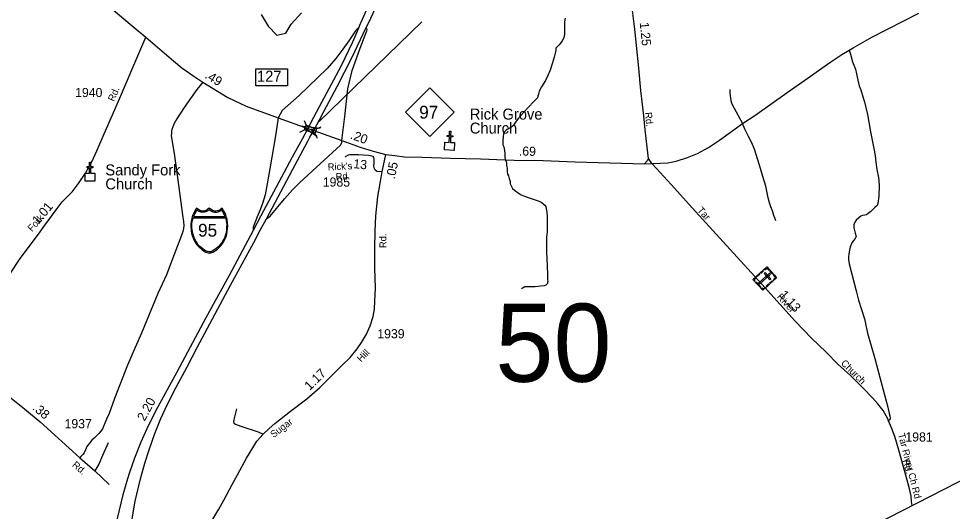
# Model space of a CAD drawing. Extents: x 2220236 to 2384410, y 720751 to 894131.
# Drawn here: x 2299448 to 2312183, y 756055 to 762781 of the extents above; entities that cross this region are included whole.
import ezdxf

# ---------------------------------------------------------------- set-up
doc = ezdxf.new("R2010")
doc.units = 0
for name, color, linetype in [('Exist Boundary Political CountyLine', 7, 'Continuous'), ('Exist Cultural Cemetery CELL', 7, 'Continuous'), ('Exist Cultural Church CELL', 7, 'Continuous'), ('Exist Cultural Church Label', 7, 'Continuous'), ('Exist Hydrographic Pond Under 1500 Sq Ft', 7, 'Continuous'), ('Exist Road Non-System Type 51', 7, 'Continuous'), ('Exist Road Non-System Type 51 Label', 7, 'Continuous'), ('Exist Road Primary Interstate Divided Center Attributed', 7, 'Continuous'), ('Exist Road Primary Interstate Interchange CELL', 7, 'Continuous'), ('Exist Road Primary Interstate Mileage Hundredths English Label', 7, 'Continuous'), ('Exist Road Primary Interstate Ramp 1 Lane Attributed', 7, 'Continuous'), ('Exist Road Primary Interstate Shield CELL', 7, 'Continuous'), ('Exist Road Primary Interstate Shield Number Label', 7, 'Continuous'), ('Exist Road Primary NC Attributed', 7, 'Continuous'), ('Exist Road Primary NC Service Mileage Hundredths English Label', 7, 'Continuous'), ('Exist Road Primary NC Shield CELL', 7, 'Continuous'), ('Exist Road Primary NC Shield Number Label', 7, 'Continuous'), ('Exist Road Primary NC Structure Standard Bridge CELL', 7, 'Continuous'), ('Exist Road Secondary Mileage Hundredths English Label', 7, 'Continuous'), ('Exist Road Secondary Structure Standard Bridge Attributed CELL', 7, 'Continuous'), ('Exist Road Secondary Structure Standard Bridge Number Label', 7, 'Continuous'), ('Exist Road Secondary Type 51 Attributed', 7, 'Continuous'), ('Exist Road Secondary Type 51 Label', 7, 'Continuous'), ('Exist Road Secondary Type 51 Number Label', 7, 'Continuous')]:
    doc.layers.add(name, color=color, linetype=linetype)

msp = doc.modelspace()

# ---------------------------------------------------------------- linework, layer by layer
at = {"layer": 'Exist Boundary Political CountyLine'}
msp.add_lwpolyline([(2324918, 762929), (2323369, 762135), (2322391, 761632), (2321693, 761275), (2320800, 760815), (2319981, 760403), (2317987, 759382), (2316918, 758831), (2315940, 758332), (2312438, 756546), (2310566, 755586), (2308713, 754646), (2307603, 754075), (2306331, 753423), (2305629, 753064), (2303724, 752098), (2302269, 751355), (2301514, 750963), (2300820, 750611), (2300140, 750264), (2297549, 748943)], dxfattribs=at)
at = {"layer": 'Exist Cultural Cemetery CELL'}
for points in [[(2309652, 759392), (2309786, 759245), (2309598, 759073), (2309464, 759220)], [(2309620, 759363), (2309627, 759354), (2309651, 759376), (2309678, 759346), (2309687, 759354), (2309652, 759392)], [(2309515, 759267), (2309547, 759297), (2309555, 759288), (2309523, 759259)], [(2309704, 759292), (2309691, 759306), (2309541, 759169), (2309554, 759155)], [(2309565, 759313), (2309597, 759342), (2309604, 759334), (2309573, 759304)], [(2309629, 759316), (2309615, 759303), (2309695, 759217), (2309708, 759229)], [(2309702, 759337), (2309737, 759299), (2309728, 759292), (2309693, 759330)], [(2309754, 759216), (2309746, 759224), (2309770, 759246), (2309743, 759276), (2309751, 759283), (2309786, 759245)], [(2309486, 759196), (2309495, 759204), (2309480, 759220), (2309510, 759247), (2309502, 759255), (2309464, 759220)], [(2309511, 759185), (2309568, 759123), (2309560, 759115), (2309503, 759178)], [(2309644, 759130), (2309676, 759160), (2309683, 759151), (2309651, 759122)], [(2309692, 759175), (2309724, 759204), (2309732, 759196), (2309700, 759167)], [(2309576, 759098), (2309584, 759105), (2309599, 759089), (2309629, 759117), (2309636, 759108), (2309598, 759073)]]:
    msp.add_lwpolyline(points, close=True, dxfattribs=at)
at = {"layer": 'Exist Cultural Church CELL'}
for points in [[(2305263, 761094), (2305320, 761092), (2305323, 761168), (2305291, 761170), (2305291, 761186), (2305323, 761184), (2305326, 761244), (2305342, 761244), (2305339, 761184), (2305371, 761182), (2305371, 761166), (2305339, 761168), (2305336, 761092), (2305393, 761089), (2305389, 760983), (2305258, 760988)], [(2300356, 760670), (2300413, 760670), (2300413, 760746), (2300381, 760746), (2300381, 760762), (2300413, 760762), (2300413, 760822), (2300429, 760822), (2300429, 760762), (2300461, 760762), (2300461, 760746), (2300429, 760746), (2300429, 760670), (2300487, 760670), (2300487, 760563), (2300356, 760563)]]:
    msp.add_lwpolyline(points, close=True, dxfattribs=at)
at = {"layer": 'Exist Hydrographic Pond Under 1500 Sq Ft'}
for points in [[(2302756, 762838), (2302849, 762677), (2302967, 762554)], [(2302967, 762554), (2303092, 762582), (2303166, 762707), (2303306, 762860)]]:
    msp.add_lwpolyline(points, dxfattribs=at)
at = {"layer": 'Exist Road Non-System Type 51'}
msp.add_line((2300683, 756421), (2300487, 756607), dxfattribs=at)
for points in [[(2306903, 762788), (2306892, 762741), (2306891, 762695), (2306891, 762641), (2306892, 762598), (2306891, 762569), (2306882, 762519), (2306863, 762478), (2306840, 762445), (2306819, 762423), (2306794, 762396), (2306773, 762377), (2306773, 762353), (2306767, 762310), (2306753, 762257), (2306724, 762164), (2306698, 762076), (2306666, 762005), (2306632, 761935), (2306581, 761852), (2306547, 761792), (2306544, 761775), (2306537, 761747), (2306531, 761722), (2306523, 761701), (2306508, 761684), (2306472, 761645), (2306336, 761500), (2306264, 761424), (2306234, 761382), (2306214, 761353), (2306198, 761329), (2306189, 761316), (2306172, 761300), (2306142, 761288), (2306120, 761273), (2306096, 761258), (2306083, 761245), (2306072, 761230), (2306062, 761205), (2306058, 761170), (2306051, 761111), (2306053, 761060), (2306067, 761029), (2306075, 760982), (2306078, 760941), (2306080, 760903), (2306082, 760855)], [(2310776, 762352), (2310796, 762295), (2310823, 762190), (2310864, 762092), (2310876, 762030), (2310896, 761940), (2310913, 761866), (2310933, 761809), (2310968, 761702), (2310986, 761647), (2311000, 761586), (2311026, 761472), (2311044, 761367), (2311068, 761237), (2311104, 761055), (2311119, 760985), (2311130, 760907), (2311138, 760824), (2311154, 760721), (2311175, 760611), (2311183, 760508), (2311179, 760359), (2311169, 760256), (2311157, 760232), (2311127, 760202), (2311073, 760147), (2311037, 760119), (2311011, 760105), (2310989, 760098), (2310957, 760092), (2310934, 760083), (2310907, 760061), (2310873, 760030), (2310847, 759995), (2310841, 759966), (2310838, 759926), (2310847, 759891), (2310857, 759853), (2310871, 759808), (2310868, 759796), (2310859, 759782), (2310834, 759754), (2310813, 759719), (2310790, 759665), (2310776, 759600), (2310772, 759565), (2310768, 759530), (2310768, 759495), (2310776, 759434), (2310809, 759310), (2310873, 759065), (2310904, 758937), (2310983, 758683), (2311026, 758487), (2311127, 758142), (2311207, 757834), (2311302, 757479), (2311321, 757393), (2311331, 757357), (2311334, 757324), (2311333, 757314), (2311327, 757303), (2311314, 757290)], [(2301961, 761913), (2301880, 761815), (2301707, 761570), (2301607, 761415), (2301568, 761348), (2301549, 761304), (2301538, 761269), (2301531, 761246), (2301531, 761213), (2301529, 761181), (2301568, 760939), (2301623, 760545), (2301688, 760066), (2301697, 760011), (2301700, 759958), (2301695, 759916), (2301686, 759877), (2301658, 759796), (2301570, 759560), (2301464, 759282), (2301346, 759028), (2301198, 758667), (2301124, 758487), (2301036, 758293), (2300934, 758050), (2300756, 757596), (2300684, 757390), (2300647, 757314), (2300615, 757235), (2300590, 757182), (2300569, 757149), (2300542, 757118), (2300510, 757086), (2300481, 757059), (2300444, 757027), (2300416, 756987), (2300379, 756939), (2300358, 756897), (2300340, 756855), (2300324, 756832), (2300298, 756805), (2300283, 756786)], [(2309149, 761812), (2309150, 761764), (2309161, 761664), (2309169, 761634), (2309184, 761598), (2309206, 761560), (2309323, 761348)], [(2309776, 760023), (2309763, 760064), (2309749, 760094), (2309737, 760126), (2309728, 760156), (2309709, 760211), (2309687, 760267), (2309669, 760336), (2309659, 760405), (2309638, 760494), (2309596, 760627), (2309551, 760783), (2309527, 760869), (2309489, 760985), (2309447, 761086), (2309401, 761172), (2309354, 761271), (2309323, 761348)], [(2306082, 760855), (2306096, 760830), (2306103, 760811), (2306104, 760777), (2306109, 760740), (2306110, 760696), (2306117, 760660), (2306129, 760635), (2306139, 760600), (2306142, 760584), (2306150, 760559), (2306154, 760525), (2306166, 760497), (2306185, 760464), (2306213, 760438), (2306260, 760405), (2306302, 760378), (2306346, 760357), (2306409, 760333), (2306481, 760313), (2306536, 760295), (2306573, 760278), (2306595, 760262), (2306608, 760250), (2306623, 760237), (2306637, 760215), (2306644, 760184), (2306652, 760140), (2306656, 760079), (2306658, 759987), (2306657, 759873), (2306649, 759799), (2306648, 759676), (2306649, 759594), (2306656, 759414), (2306660, 759277), (2306662, 759221), (2306664, 759192), (2306662, 759179), (2306660, 759166), (2306649, 759151), (2306637, 759141), (2306616, 759133), (2306565, 759128), (2306494, 759121), (2306384, 759121), (2306350, 759118), (2306329, 759108), (2306311, 759095), (2306306, 759089)], [(2308038, 760873), (2308021, 760842), (2307984, 760801)], [(2302417, 757456), (2302394, 757345), (2302377, 757280), (2302383, 757257), (2302405, 757246), (2302479, 757216), (2302713, 757139), (2302781, 757109)], [(2300667, 756991), (2300593, 756816), (2300540, 756699), (2300487, 756607)]]:
    msp.add_lwpolyline(points, dxfattribs=at)
at = {"layer": 'Exist Road Primary Interstate Divided Center Attributed'}
for points in [[(2305039, 765388), (2304961, 765138), (2304756, 764498), (2304486, 763661), (2304332, 763236), (2304205, 762933), (2304113, 762728), (2304106, 762711), (2304081, 762649)], [(2304190, 762659), (2304219, 762721), (2304283, 762854), (2304445, 763270), (2304631, 763804), (2304892, 764518), (2305142, 765211), (2305198, 765358)], [(2304081, 762649), (2304003, 762458), (2303840, 762130), (2303579, 761638), (2303471, 761431), (2303393, 761281)], [(2303472, 761255), (2303550, 761400), (2303612, 761514), (2303794, 761854), (2303993, 762245), (2304190, 762659)], [(2303393, 761281), (2303313, 761136), (2303179, 760892), (2302960, 760479), (2302752, 760091), (2302646, 759891)], [(2302829, 760047), (2303183, 760717), (2303391, 761107), (2303419, 761161), (2303472, 761255)], [(2300748, 753112), (2300757, 753228), (2300811, 753888), (2300867, 754590), (2300917, 755169), (2300940, 755506), (2300988, 755899), (2301038, 756192), (2301108, 756498), (2301167, 756711), (2301226, 756897), (2301305, 757119), (2301386, 757321), (2301479, 757520), (2301591, 757740), (2301746, 758029), (2301883, 758290), (2302338, 759141), (2302655, 759726), (2302744, 759892), (2302829, 760047)], [(2302646, 759891), (2302317, 759273), (2302003, 758695), (2301605, 757953), (2301316, 757422), (2301195, 757183), (2301114, 757001), (2301030, 756782), (2300957, 756571), (2300934, 756501), (2300870, 756279), (2300788, 755939), (2300727, 755610), (2300687, 755220), (2300662, 754523), (2300659, 753865), (2300646, 753144)]]:
    msp.add_lwpolyline(points, dxfattribs=at)
at = {"layer": 'Exist Road Primary Interstate Interchange CELL'}
msp.add_lwpolyline([(2302681, 762098), (2303116, 762098), (2303116, 761865), (2302681, 761865)], close=True, dxfattribs=at)
at = {"layer": 'Exist Road Primary Interstate Ramp 1 Lane Attributed'}
for points in [[(2304081, 762649), (2304059, 762634), (2304042, 762613), (2303952, 762477), (2303871, 762365), (2303774, 762239), (2303656, 762101), (2303275, 761733), (2303040, 761526), (2302989, 761428)], [(2303858, 761117), (2303899, 761444), (2303937, 761821), (2303996, 762071), (2304106, 762380), (2304196, 762613), (2304200, 762634), (2304190, 762659)], [(2302989, 761428), (2302949, 761181), (2302873, 760733), (2302839, 760525), (2302808, 760377), (2302774, 760259), (2302742, 760172), (2302703, 760076), (2302645, 759935), (2302646, 759891)], [(2302829, 760047), (2302880, 760083), (2303072, 760323), (2303182, 760445), (2303285, 760544), (2303837, 761052), (2303854, 761084), (2303858, 761117)]]:
    msp.add_lwpolyline(points, dxfattribs=at)
at = {"layer": 'Exist Road Primary Interstate Shield CELL'}
for points in [[(2302048, 759581), (2302058, 759582), (2302070, 759585), (2302083, 759589), (2302097, 759595), (2302118, 759607), (2302134, 759616), (2302154, 759629), (2302180, 759653), (2302206, 759681), (2302229, 759712), (2302247, 759741), (2302263, 759774), (2302277, 759805), (2302287, 759840), (2302294, 759874), (2302298, 759910), (2302300, 759949), (2302298, 759994), (2302290, 760040), (2302283, 760068), (2302272, 760102), (2302263, 760124), (2302242, 760162), (2302223, 760192), (2302196, 760172), (2302178, 760163), (2302167, 760158), (2302156, 760156), (2302136, 760153), (2302123, 760154), (2302111, 760157), (2302101, 760159), (2302092, 760163), (2302048, 760192), (2302004, 760163), (2301995, 760159), (2301985, 760157), (2301976, 760154), (2301961, 760153), (2301949, 760154), (2301937, 760156), (2301928, 760158), (2301917, 760163), (2301872, 760192), (2301855, 760166), (2301840, 760140), (2301825, 760105), (2301815, 760077), (2301808, 760054), (2301800, 760012), (2301796, 759975), (2301795, 759949), (2301800, 759885), (2301807, 759851), (2301814, 759823), (2301838, 759763), (2301856, 759729), (2301871, 759705), (2301893, 759678), (2301905, 759665), (2301949, 759626), (2301979, 759605), (2302003, 759592), (2302014, 759588), (2302032, 759583)], [(2301878, 760171), (2301867, 760154), (2301854, 760131), (2301844, 760107), (2301834, 760081), (2302265, 760081), (2302255, 760104), (2302244, 760126), (2302233, 760147), (2302219, 760167), (2302195, 760151), (2302178, 760143), (2302163, 760138), (2302151, 760135), (2302133, 760134), (2302124, 760134), (2302099, 760140), (2302081, 760147), (2302064, 760159), (2302051, 760171), (2302017, 760151), (2302001, 760144), (2301984, 760139), (2301965, 760137), (2301935, 760140), (2301912, 760148), (2301892, 760159)], [(2302268, 760060), (2302272, 760048), (2302279, 760021), (2302282, 760000), (2302285, 759976), (2302284, 759935), (2302282, 759892), (2302278, 759867), (2302273, 759844), (2302266, 759818), (2302254, 759785), (2302239, 759756), (2302219, 759724), (2302197, 759696), (2302188, 759685), (2302170, 759666), (2302138, 759640), (2302114, 759623), (2302086, 759606), (2302072, 759600), (2302055, 759596), (2302042, 759597), (2302025, 759601), (2302011, 759605), (2301982, 759621), (2301958, 759637), (2301918, 759670), (2301897, 759695), (2301877, 759724), (2301859, 759754), (2301840, 759794), (2301826, 759834), (2301817, 759877), (2301810, 759929), (2301809, 759962), (2301811, 759992), (2301814, 760009), (2301818, 760029), (2301826, 760060)]]:
    msp.add_lwpolyline(points, close=True, dxfattribs=at)
at = {"layer": 'Exist Road Primary NC Attributed'}
for points in [[(2299124, 764099), (2299686, 763691), (2300028, 763439), (2300272, 763253), (2300711, 762924), (2300998, 762685), (2301184, 762528)], [(2308085, 760803), (2308200, 760806), (2308304, 760815), (2308417, 760835), (2308572, 760885), (2308707, 760942), (2308858, 761023), (2309007, 761123), (2309323, 761348), (2309487, 761460), (2309932, 761773), (2310173, 761943), (2310526, 762193), (2310676, 762293), (2310776, 762352), (2310831, 762384), (2311086, 762527), (2311724, 762856)], [(2301184, 762528), (2301403, 762338), (2301559, 762206), (2301674, 762111), (2301835, 761997), (2301961, 761913), (2302299, 761704), (2302550, 761585), (2302989, 761428)], [(2302989, 761428), (2303393, 761281)], [(2303393, 761281), (2303433, 761268), (2303472, 761255)], [(2303472, 761255), (2303858, 761117)], [(2303858, 761117), (2304105, 761027), (2304284, 760974), (2304455, 760928)], [(2304455, 760928), (2304577, 760911), (2304709, 760896), (2304953, 760890), (2305340, 760877), (2305747, 760866), (2306082, 760855), (2306206, 760851), (2306602, 760843), (2307040, 760828), (2307984, 760801), (2308085, 760803)]]:
    msp.add_lwpolyline(points, dxfattribs=at)
at = {"layer": 'Exist Road Primary NC Service Mileage Hundredths English Label'}
msp.add_line((2303547, 761377), (2304946, 762738), dxfattribs=at)
at = {"layer": 'Exist Road Primary NC Shield CELL'}
msp.add_lwpolyline([(2304724, 761505), (2305057, 761838), (2305390, 761505), (2305057, 761172)], close=True, dxfattribs=at)
at = {"layer": 'Exist Road Primary NC Structure Standard Bridge CELL'}
for p, q in [((2303341, 761390), (2303370, 761328)), ((2303512, 761276), (2303575, 761305)), ((2303284, 761232), (2303346, 761261)), ((2303489, 761211), (2303518, 761149))]:
    msp.add_line(p, q, dxfattribs=at)
msp.add_lwpolyline([(2303370, 761328), (2303512, 761276), (2303488, 761210), (2303346, 761261)], close=True, dxfattribs=at)
at = {"layer": 'Exist Road Secondary Structure Standard Bridge Attributed CELL'}
msp.add_lwpolyline([(2303515, 761170), (2303317, 761312), (2303559, 761288), (2303431, 761269)], close=True, dxfattribs=at)
at = {"layer": 'Exist Road Secondary Type 51 Attributed'}
for points in [[(2308085, 760803), (2308038, 760873), (2308020, 761028), (2307994, 761262), (2307974, 761454), (2307955, 761610), (2307936, 761799), (2307905, 762107), (2307851, 762638), (2307814, 762930), (2307800, 763044), (2307767, 763232), (2307721, 763500), (2307690, 763681), (2307666, 763795), (2307651, 763850), (2307599, 763992), (2307550, 764085), (2307507, 764151), (2307471, 764194), (2307423, 764248), (2307321, 764361), (2307184, 764511), (2307047, 764657)], [(2298931, 757827), (2298927, 758158), (2298927, 758421), (2298938, 758567), (2298962, 758661), (2299011, 758768), (2299195, 759093), (2299468, 759506), (2299719, 759837), (2299795, 759946), (2299872, 760051), (2299947, 760153), (2300042, 760280), (2300182, 760421), (2300266, 760530), (2300358, 760671), (2300411, 760761), (2300445, 760827), (2300516, 760977), (2300614, 761210), (2300824, 761686), (2301021, 762146), (2301184, 762528)], [(2304408, 760693), (2304363, 760691), (2304337, 760693), (2304327, 760700), (2304312, 760713), (2304302, 760732), (2304294, 760765), (2304295, 760806), (2304299, 760835), (2304299, 760863), (2304294, 760884), (2304282, 760897), (2304265, 760905), (2304219, 760911), (2304147, 760916), (2304081, 760922), (2303988, 760924), (2303965, 760924), (2303944, 760917), (2303912, 760897), (2303902, 760889)], [(2304408, 760693), (2304412, 760711), (2304455, 760928)], [(2311633, 756133), (2311628, 756190), (2311620, 756262), (2311592, 756379), (2311538, 756582), (2311451, 756892), (2311397, 757078), (2311355, 757197), (2311314, 757290), (2311302, 757319), (2311238, 757430), (2311169, 757521), (2311096, 757606), (2310966, 757736), (2310793, 757910), (2310619, 758065), (2310462, 758226), (2310264, 758419), (2310039, 758651), (2309585, 759157), (2309154, 759631), (2308680, 760148), (2308349, 760515), (2308148, 760736), (2308085, 760803)], [(2302098, 755950), (2302179, 756086), (2302245, 756206), (2302361, 756420), (2302433, 756553), (2302554, 756780), (2302642, 756923), (2302697, 757013), (2302736, 757060), (2302781, 757109), (2302864, 757188), (2302944, 757253), (2303155, 757422), (2303380, 757593), (2303557, 757747), (2303717, 757903), (2303858, 758048), (2303968, 758155), (2304066, 758273), (2304126, 758359), (2304192, 758476), (2304243, 758588), (2304282, 758716), (2304301, 758817), (2304305, 758928), (2304314, 759103), (2304308, 759379), (2304305, 759649), (2304310, 759878), (2304318, 760087), (2304348, 760351), (2304384, 760556), (2304408, 760693)], [(2298931, 757827), (2299033, 757799), (2299112, 757767), (2299170, 757734), (2299211, 757711), (2299527, 757454), (2299740, 757276), (2300283, 756786), (2300487, 756607)]]:
    msp.add_lwpolyline(points, dxfattribs=at)

# ---------------------------------------------------------------- texts
at = {"layer": 'Exist Cultural Church Label'}
for s, p in [('Rick Grove', (2305601, 761403)), ('Church', (2305601, 761212)), ('Sandy Fork', (2300630, 760641)), ('Church', (2300630, 760450))]:
    msp.add_text(s, height=150, dxfattribs=at).set_placement(p)
at = {"layer": 'Exist Road Non-System Type 51 Label'}
msp.add_text('Tar River Ch Rd', height=95, rotation=284.4438, dxfattribs=at).set_placement((2311441, 757108))
at = {"layer": 'Exist Road Primary Interstate Interchange CELL'}
msp.add_text('127', height=150, dxfattribs=at).set_placement((2302699, 761920))
at = {"layer": 'Exist Road Primary Interstate Mileage Hundredths English Label'}
msp.add_text('2.20', height=125, rotation=61.4241, dxfattribs=at).set_placement((2301166, 757278))
at = {"layer": 'Exist Road Primary Interstate Shield Number Label'}
msp.add_text('95', height=175, dxfattribs=at).set_placement((2301895, 759805))
at = {"layer": 'Exist Road Primary NC Service Mileage Hundredths English Label'}
for s, rotation, p in [('.49', 328.2373, (2301977, 761977)), ('.20', 340.007, (2303962, 761146)), ('.69', 358.7606, (2306270, 760912))]:
    msp.add_text(s, height=125, rotation=rotation, dxfattribs=at).set_placement(p)
at = {"layer": 'Exist Road Primary NC Shield Number Label'}
msp.add_text('97', height=175, dxfattribs=at).set_placement((2304911, 761416))
at = {"layer": 'Exist Road Secondary Mileage Hundredths English Label'}
for s, rotation, p in [('1.25', 275.9601, (2307918, 762727)), ('.13', 354.1416, (2303962, 760746)), ('.05', 78.7019, (2304578, 760584)), ('1.01', 49.9672, (2299715, 759962)), ('1.13', 312.5281, (2309816, 759003)), ('1.17', 44.244, (2303418, 757699)), ('.38', 320.0341, (2299627, 757452))]:
    msp.add_text(s, height=125, rotation=rotation, dxfattribs=at).set_placement(p)
at = {"layer": 'Exist Road Secondary Structure Standard Bridge Number Label'}
msp.add_text('50', height=1066.3, dxfattribs=at).set_placement((2305949, 757824))
at = {"layer": 'Exist Road Secondary Type 51 Label'}
for s, rotation, p in [('Rd.', 66.1365, (2300747, 761643)), ('Rd.', 275.5818, (2307990, 761500)), ("Rick's", 2.9203, (2303666, 760708)), ('Rd.', 2.9203, (2303774, 760576)), ('Tar', 312.396, (2308697, 760160)), ('Fork', 47.8643, (2299629, 759866)), ('Rd.', 90.6211, (2304464, 759650)), ('River', 312.5025, (2309783, 758978)), ('Hill', 46.2364, (2304120, 758086)), ('Church', 315.2094, (2310656, 758069)), ('Sugar', 37.1226, (2302925, 757054)), ('Rd.', 319.4554, (2300170, 756676)), ('Rd.', 285.6613, (2311503, 756750))]:
    msp.add_text(s, height=95, rotation=rotation, dxfattribs=at).set_placement(p)
at = {"layer": 'Exist Road Secondary Type 51 Number Label'}
for s, p in [('1940', (2300218, 761710)), ('1985', (2303596, 760488)), ('1939', (2304340, 758417)), ('1937', (2300074, 757189)), ('1981', (2311543, 757008))]:
    msp.add_text(s, height=125, dxfattribs=at).set_placement(p)

doc.saveas('drawing.dxf')
